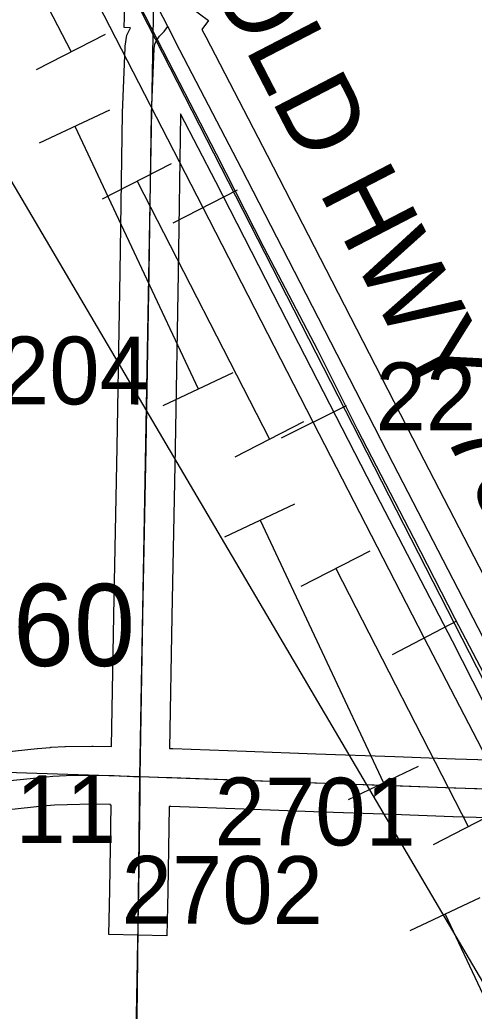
# Model space of a CAD drawing. Extents: x -157.2 to -99.3, y 12.2 to 46.2.
# Drawn here: x -143.974 to -143.504, y 24.899 to 25.924 of the extents above; entities that cross this region are included whole.
import ezdxf

# ---------------------------------------------------------------- set-up
doc = ezdxf.new("R2010")
doc.units = 0
for name, color, linetype in [('tdCoPipe', 7, 'Continuous'), ('tdCoPipe1', 7, 'Continuous'), ('tdCoPipe2', 7, 'Continuous'), ('tdCoRRCL', 7, 'Continuous'), ('tdCoSecRdNmbr', 7, 'Continuous'), ('tdCoSecRdTxt', 7, 'Continuous'), ('tdCoSecRteBand', 7, 'Continuous'), ('tdCoSecRteCL', 7, 'Continuous'), ('tdCoSectLine', 7, 'Continuous'), ('tdCoSectLinePart', 7, 'Continuous'), ('tdCoStrucSecFHWANum', 7, 'Continuous'), ('tdCoSurfAsphalt', 7, 'Continuous'), ('tdCoSurfConc', 7, 'Continuous'), ('tdCoSurfGravel', 7, 'Continuous'), ('tdCoSurfLNO', 7, 'Continuous')]:
    doc.layers.add(name, color=color, linetype=linetype)

msp = doc.modelspace()

# ---------------------------------------------------------------- linework, layer by layer
at = {"layer": 'tdCoPipe'}
msp.add_lwpolyline([(-144.5317, 38.1832), (-143.5928, 36.8918), (-143.6099, 34.8602), (-143.4402, 34.5415), (-143.5694, 34.3304), (-143.5634, 33.7239), (-143.4667, 33.4993), (-143.5656, 33.4168), (-143.4755, 33.1706), (-143.455, 32.2186), (-143.5122, 31.3968), (-143.6938, 30.9939), (-143.6811, 29.9265), (-143.7347, 27.6406), (-143.7362, 26.8708), (-143.9217, 26.7732), (-143.8183, 26.5085), (-143.8116, 26.1034), (-144.0839, 25.9289), (-143.0557, 24.1836)], dxfattribs=at)
at = {"layer": 'tdCoPipe1'}
for p, q in [((-143.9564, 25.8724), (-143.8851, 25.909)), ((-143.888, 25.7389), (-143.8166, 25.7755)), ((-143.751, 25.472), (-143.6797, 25.5086)), ((-143.6826, 25.3385), (-143.6112, 25.3751)), ((-143.5457, 25.0716), (-143.4743, 25.1082))]:
    msp.add_line(p, q, dxfattribs=at)
for points in [[(-143.8609, 26.1163), (-143.8583, 26.0456), (-143.9677, 25.9822), (-143.9207, 25.8907)], [(-143.8523, 25.7572), (-143.7154, 25.4903)], [(-143.6469, 25.3568), (-143.51, 25.0899)]]:
    msp.add_lwpolyline(points, dxfattribs=at)
at = {"layer": 'tdCoPipe2'}
for p, q in [((-143.9532, 25.7967), (-143.8807, 25.8308)), ((-143.8254, 25.5253), (-143.7529, 25.5594)), ((-143.7615, 25.3896), (-143.689, 25.4237)), ((-143.6337, 25.1181), (-143.5612, 25.1523)), ((-143.5698, 24.9824), (-143.4973, 25.0166))]:
    msp.add_line(p, q, dxfattribs=at)
for points in [[(-143.9169, 25.8138), (-143.7891, 25.5424)], [(-143.7252, 25.4066), (-143.5975, 25.1352)], [(-143.5336, 24.9995), (-143.4557, 24.8341), (-143.4009, 24.7305)]]:
    msp.add_lwpolyline(points, dxfattribs=at)
at = {"layer": 'tdCoRRCL'}
for p, q in [((-143.7487, 25.7478), (-143.8155, 25.7137)), ((-143.6362, 25.525), (-143.7033, 25.4914)), ((-143.5219, 25.3022), (-143.5884, 25.2675))]:
    msp.add_line(p, q, dxfattribs=at)
for points in [[(-142.7262, 23.739), (-143.1704, 24.6), (-143.4255, 25.1074), (-144.37, 26.9512), (-144.9761, 28.127), (-145.218, 28.6071), (-145.4618, 29.0746), (-145.6726, 29.4889)], [(-142.984, 24.1736), (-143.0984, 24.3958), (-143.2126, 24.6181), (-143.3271, 24.8407), (-143.4403, 25.0634), (-143.5554, 25.2851), (-143.6701, 25.5081), (-143.7843, 25.7301), (-143.8986, 25.9522), (-144.0122, 26.1747), (-144.1269, 26.3975), (-144.241, 26.6197), (-144.3551, 26.8418), (-144.4697, 27.0637), (-144.5841, 27.286), (-144.6989, 27.509), (-144.8132, 27.7309), (-144.9272, 27.9528), (-145.0424, 28.1754), (-145.1566, 28.3975), (-145.2703, 28.62), (-145.3849, 28.8426), (-145.4992, 29.0643), (-145.6132, 29.2868)], [(-142.9429, 24.1755), (-142.9806, 24.2489), (-143.0365, 24.3577), (-143.039, 24.3626), (-143.0771, 24.4361), (-143.1345, 24.548), (-143.1683, 24.6141), (-143.2176, 24.7085), (-143.2338, 24.741), (-143.2719, 24.8152), (-143.3327, 24.9339), (-143.3898, 25.047), (-143.3969, 25.061), (-143.4255, 25.1164), (-143.4603, 25.1843), (-143.5233, 25.3046), (-143.5662, 25.3882), (-143.6239, 25.4996), (-143.6467, 25.5451), (-143.6653, 25.5824), (-143.7209, 25.6883), (-143.7702, 25.7851), (-143.8195, 25.8805), (-143.8562, 25.9518)]]:
    msp.add_lwpolyline(points, dxfattribs=at)
at = {"layer": 'tdCoSecRteBand'}
for points in [[(-144.0042, 25.1656), (-143.9559, 25.1707), (-143.9556, 25.1707), (-143.9553, 25.1707), (-143.9423, 25.1718), (-143.9417, 25.1719), (-143.9412, 25.1719), (-143.9272, 25.1726), (-143.9268, 25.1726), (-143.9264, 25.1726), (-143.8992, 25.1731), (-143.8985, 25.1732), (-143.8978, 25.1731), (-143.8788, 25.1726), (-143.8764, 25.3082), (-143.8764, 25.3083), (-143.8764, 25.3083), (-143.873, 25.4821), (-143.87, 25.6633), (-143.8675, 25.827), (-143.8675, 25.8274), (-143.8675, 25.8278), (-143.8648, 25.8953), (-143.8647, 25.8971), (-143.8645, 25.8988), (-143.8637, 25.9035), (-143.863, 25.9081), (-143.8609, 25.9122), (-143.8592, 25.9156), (-143.8659, 25.9159), (-143.8649, 25.938)], [(-143.797, 25.9368), (-143.7785, 25.9231), (-143.7853, 25.914), (-143.7814, 25.9063), (-143.7178, 25.7841), (-143.7178, 25.784), (-143.7177, 25.7839), (-143.6509, 25.654), (-143.6509, 25.654), (-143.6509, 25.654), (-143.6188, 25.5916), (-143.5609, 25.4789), (-143.4729, 25.3091)], [(-143.4634, 25.1582), (-143.5262, 25.2815), (-143.6142, 25.4514), (-143.6142, 25.4514), (-143.6142, 25.4514), (-143.6722, 25.5641), (-143.6722, 25.5641), (-143.6722, 25.5642), (-143.7043, 25.6265), (-143.771, 25.7564), (-143.8075, 25.8265), (-143.8075, 25.8257), (-143.81, 25.6624), (-143.81, 25.6623), (-143.81, 25.6623), (-143.813, 25.4811), (-143.813, 25.481), (-143.813, 25.481), (-143.8164, 25.3071), (-143.8188, 25.1707), (-143.8184, 25.1707), (-143.8154, 25.1706), (-143.8154, 25.1706), (-143.8153, 25.1706), (-143.7396, 25.1679), (-143.7396, 25.1679), (-143.7396, 25.1679), (-143.6674, 25.1651), (-143.5858, 25.1624), (-143.5857, 25.1624), (-143.5856, 25.1624), (-143.5234, 25.16), (-143.4644, 25.1583)], [(-143.4661, 25.0983), (-143.5253, 25.1), (-143.5255, 25.1), (-143.5256, 25.1), (-143.5879, 25.1025), (-143.6694, 25.1052), (-143.6695, 25.1052), (-143.6696, 25.1052), (-143.7418, 25.1079), (-143.8174, 25.1106), (-143.8193, 25.1107), (-143.8207, 25.0236), (-143.8207, 25.0236), (-143.8207, 25.0235), (-143.821, 25.0072), (-143.821, 25.0072), (-143.821, 25.0072), (-143.821, 25.0072), (-143.8215, 24.9772), (-143.8815, 24.9783), (-143.881, 25.0083), (-143.8807, 25.0246), (-143.8793, 25.1122), (-143.8799, 25.1122), (-143.8798, 25.1127), (-143.8987, 25.1131), (-143.9248, 25.1126), (-143.9378, 25.112), (-143.95, 25.111), (-143.9983, 25.1059)]]:
    msp.add_lwpolyline(points, dxfattribs=at)
at = {"layer": 'tdCoSecRteCL'}
msp.add_line((-143.8205, 25.917), (-143.8346, 25.9446), dxfattribs=at)
for points in [[(-143.8493, 25.1417), (-143.8464, 25.3077), (-143.843, 25.4815), (-143.84, 25.6628), (-143.8375, 25.8266), (-143.8348, 25.8941), (-143.8341, 25.8988), (-143.8324, 25.9023), (-143.8292, 25.9069), (-143.827, 25.9091), (-143.8245, 25.9116), (-143.8205, 25.917)], [(-143.4132, 25.1267), (-143.4327, 25.1641), (-143.4995, 25.2953), (-143.5876, 25.4652), (-143.6455, 25.5779), (-143.6776, 25.6403), (-143.7444, 25.7702), (-143.808, 25.8925), (-143.8205, 25.917)], [(-144.6448, 25.1592), (-144.6179, 25.1543), (-144.6005, 25.1519), (-144.5788, 25.1499), (-144.5785, 25.1499), (-144.5423, 25.1475), (-144.5226, 25.147), (-144.4941, 25.1459), (-144.3873, 25.1424), (-144.154, 25.1349), (-144.1023, 25.1329), (-144.0797, 25.1322), (-144.0554, 25.132), (-144.024, 25.134), (-144.0014, 25.1358), (-143.9528, 25.1408), (-143.9397, 25.142), (-143.9258, 25.1426), (-143.8986, 25.1431), (-143.8761, 25.1426), (-143.856, 25.1419), (-143.8493, 25.1417)], [(-143.851, 25.0077), (-143.851, 25.0077), (-143.8507, 25.0241), (-143.8491, 25.1237), (-143.8493, 25.1417)], [(-143.8493, 25.1417), (-143.8221, 25.1408), (-143.8164, 25.1406), (-143.7407, 25.1379), (-143.6684, 25.1352), (-143.5868, 25.1325), (-143.5244, 25.13), (-143.4652, 25.1283), (-143.4132, 25.1267)]]:
    msp.add_lwpolyline(points, dxfattribs=at)
at = {"layer": 'tdCoSectLine'}
for points in [[(-143.8497, 25.1417), (-143.8312, 26.1559)], [(-144.8508, 25.1741), (-143.8497, 25.1417)], [(-143.8607, 24.1421), (-143.8497, 25.1417)], [(-143.8497, 25.1417), (-142.8498, 25.106)]]:
    msp.add_lwpolyline(points, dxfattribs=at)
at = {"layer": 'tdCoSectLinePart'}
msp.add_lwpolyline([(-143.856, 24.5699), (-143.8515, 24.9777)], dxfattribs=at)
at = {"layer": 'tdCoSurfAsphalt'}
msp.add_lwpolyline([(-143.3051, 24.9161), (-143.3143, 24.9342), (-143.3277, 24.9603), (-143.338, 24.9803), (-143.3516, 25.0068), (-143.4036, 25.1073), (-143.4132, 25.1267), (-143.4327, 25.1641), (-143.4995, 25.2953), (-143.5876, 25.4652), (-143.6455, 25.5779), (-143.6776, 25.6403), (-143.7444, 25.7702), (-143.808, 25.8925), (-143.8205, 25.917), (-143.8346, 25.9446)], dxfattribs=at)
at = {"layer": 'tdCoSurfConc'}
msp.add_lwpolyline([(-144.4941, 25.1459), (-144.3873, 25.1424), (-144.154, 25.1349), (-144.1023, 25.1329), (-144.0797, 25.1322), (-144.0554, 25.132), (-144.024, 25.134), (-144.0014, 25.1358), (-143.9528, 25.1408), (-143.9397, 25.142), (-143.9258, 25.1426), (-143.8986, 25.1431), (-143.8761, 25.1426), (-143.856, 25.1419), (-143.8493, 25.1417), (-143.8221, 25.1408), (-143.8164, 25.1406), (-143.7407, 25.1379), (-143.6684, 25.1352), (-143.5868, 25.1325), (-143.5244, 25.13), (-143.4652, 25.1283), (-143.4132, 25.1267)], dxfattribs=at)
at = {"layer": 'tdCoSurfGravel'}
msp.add_lwpolyline([(-143.851, 25.0077), (-143.851, 25.0077), (-143.8507, 25.0241), (-143.8491, 25.1237), (-143.8493, 25.1417), (-143.8464, 25.3077), (-143.843, 25.4815), (-143.84, 25.6628), (-143.8375, 25.8266), (-143.8348, 25.8941), (-143.8341, 25.8988), (-143.8324, 25.9023), (-143.8292, 25.9069), (-143.827, 25.9091), (-143.8245, 25.9116), (-143.8205, 25.917)], dxfattribs=at)
at = {"layer": 'tdCoSurfLNO'}
msp.add_line((-143.8568, 24.6867), (-143.851, 25.0077), dxfattribs=at)

# ---------------------------------------------------------------- texts
at = {"layer": 'tdCoSecRdNmbr'}
for s, rotation, p in [('2204', 359.8901, (-144.0474, 25.5266)), ('2210', 359.8904, (-143.6057, 25.4997)), ('2811', 359.89, (-144.0822, 25.0733)), ('2701', 359.8903, (-143.7723, 25.0707)), ('2702', 359.8902, (-143.8684, 24.9897))]:
    msp.add_text(s, height=0.07, rotation=rotation, dxfattribs=at).set_placement(p)
at = {"layer": 'tdCoSecRdTxt'}
msp.add_text('OLD HWY 75', height=0.08, rotation=297.3738, dxfattribs=at).set_placement((-143.7797, 25.9682))
at = {"layer": 'tdCoStrucSecFHWANum'}
msp.add_text('53660', height=0.085, dxfattribs=at).set_placement((-144.1705, 25.2559))

doc.saveas('drawing.dxf')
